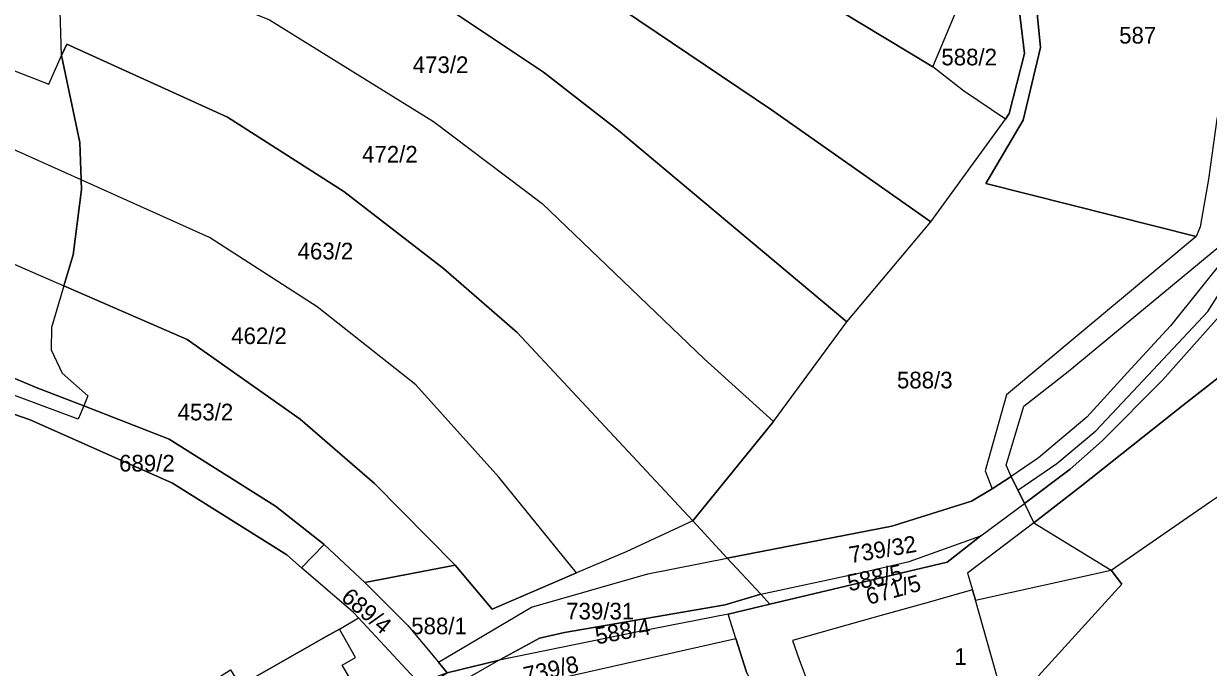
# Model space of a CAD drawing. Extents: x -629983 to -626385, y -1072828 to -1067897.
# Drawn here: x -627150.4 to -626936.7, y -1070145.8 to -1070029.7 of the extents above; entities that cross this region are included whole.
import ezdxf

# ---------------------------------------------------------------- set-up
doc = ezdxf.new("R2010")
doc.units = 0
for name, color, linetype in [('Parcela nároku', 7, 'Continuous'), ('Parcelní číslo', 7, 'Continuous'), ('Plocha PÚ', 7, 'Continuous'), ('Vnitřní obvod_šetřený', 7, 'Continuous'), ('voda', 7, 'Continuous')]:
    doc.layers.add(name, color=color, linetype=linetype)

msp = doc.modelspace()

# ---------------------------------------------------------------- linework, layer by layer
at = {"layer": 'Parcela nároku'}
for points in [[(-627088.59, -1069955.42), (-627120.01, -1069943.03), (-627122.71, -1069947.36), (-627125, -1069952.04), (-627127.45, -1069955.66), (-627129.53, -1069962.1), (-627095.01, -1069975.09), (-627066.59, -1069990.17), (-627033.45, -1070009.1), (-626986.34, -1070037.52), (-626978, -1070017.56), (-627015.68, -1069995.42)], [(-627033.45, -1070009.1), (-627066.59, -1069990.17), (-627095.01, -1069975.09), (-627129.53, -1069962.1), (-627130.33, -1069964.55), (-627134.1, -1069979.16), (-627107.13, -1069989.12), (-627073.62, -1070007.14), (-627060.19, -1070015.09), (-627015.45, -1070045.26), (-626986.73, -1070065.45), (-626973.26, -1070046.97), (-626980.83, -1070041.87), (-626986.34, -1070037.52)], [(-626986.73, -1070065.45), (-627015.45, -1070045.26), (-627060.19, -1070015.09), (-627073.62, -1070007.14), (-627107.13, -1069989.12), (-627134.1, -1069979.16), (-627138.98, -1069998.05), (-627100.4, -1070012.51), (-627079.87, -1070022.88), (-627056.59, -1070038.48), (-627043.05, -1070049), (-627001.87, -1070083.51)], [(-626958.12, -1069999.59), (-626939.49, -1069984.53), (-626922.33, -1070013.79), (-626933.64, -1070040.63), (-626935.11, -1070046.98), (-626936.62, -1070057.77), (-626938.12, -1070066.39), (-626938.87, -1070068.12), (-626976.78, -1070058.57), (-626970.06, -1070047.13), (-626966.93, -1070034), (-626969.36, -1070009.37)], [(-627138.98, -1069998.05), (-627141.62, -1070008.28), (-627142.81, -1070014.22), (-627106.07, -1070029.02), (-627076.47, -1070047.35), (-627056.84, -1070062.14), (-627027.64, -1070090.16), (-627015.09, -1070101.48), (-627001.87, -1070083.51), (-627043.05, -1070049), (-627056.59, -1070038.48), (-627079.87, -1070022.88), (-627100.4, -1070012.51)], [(-626971.36, -1070022.08), (-626969.8, -1070035.12), (-626972.59, -1070045.95), (-626973.26, -1070046.97), (-626980.83, -1070041.87), (-626986.34, -1070037.52), (-626978, -1070017.56), (-626972.67, -1070009.07)], [(-627143.19, -1070014.07), (-627158.09, -1070012.2), (-627163.38, -1070033.87), (-627145.84, -1070040.66), (-627143.56, -1070035.5), (-627143.96, -1070023.4), (-627143.3, -1070016.64), (-627142.81, -1070014.22)], [(-627027.64, -1070090.16), (-627015.09, -1070101.48), (-627029.64, -1070119.37), (-627061.35, -1070085.42), (-627074.63, -1070073.88), (-627092.65, -1070059.98), (-627113.63, -1070046.57), (-627142.64, -1070033.43), (-627143.56, -1070035.5), (-627143.96, -1070023.4), (-627143.3, -1070016.64), (-627142.81, -1070014.22), (-627106.07, -1070029.02), (-627076.47, -1070047.35), (-627056.84, -1070062.14)], [(-626921.43, -1070025.55), (-626914.75, -1070029.07), (-626920.55, -1070046.4), (-626923.16, -1070053.99), (-626928.9, -1070065.21), (-626933.01, -1070071.19), (-626943.45, -1070084.22), (-626950.65, -1070091.98), (-626958.55, -1070100.68), (-626967.28, -1070108.01), (-626972.24, -1070111.41), (-626973.1, -1070109.36), (-626969.94, -1070098.69), (-626961.92, -1070092.47), (-626932.99, -1070068.55), (-626929.34, -1070041.47)], [(-627166.71, -1070046.52), (-627163.38, -1070033.87), (-627145.84, -1070040.66), (-627143.56, -1070035.5), (-627140.29, -1070051.16), (-627140.06, -1070057.9), (-627151.83, -1070052.62)], [(-627092.65, -1070059.98), (-627074.63, -1070073.88), (-627061.35, -1070085.42), (-627029.64, -1070119.37), (-627041.71, -1070124.97), (-627050.63, -1070128.79), (-627064.7, -1070111.53), (-627079.63, -1070094.86), (-627097.43, -1070080.81), (-627116.88, -1070068.28), (-627140.06, -1070057.9), (-627140.29, -1070051.16), (-627143.56, -1070035.5), (-627142.64, -1070033.43), (-627113.63, -1070046.57)], [(-626914.83, -1070045.91), (-626916.3, -1070052.3), (-626918.02, -1070056.37), (-626926.9, -1070072.56), (-626930.91, -1070078.27), (-626944.91, -1070094), (-626955.78, -1070104.97), (-626961.55, -1070110.08), (-626969.82, -1070116.29), (-626968.13, -1070119.78), (-626959.53, -1070113.07), (-626941.17, -1070098.52), (-626930.19, -1070089.96), (-626917.66, -1070080.4), (-626903.57, -1070068.94), (-626908.7, -1070047.45), (-626911.27, -1070036.42)], [(-627140.06, -1070057.9), (-627151.83, -1070052.62), (-627166.71, -1070046.52), (-627171.49, -1070064.68), (-627143.14, -1070077), (-627141.49, -1070071.4), (-627140, -1070059.64)], [(-627141.49, -1070071.4), (-627143.14, -1070077), (-627120.88, -1070086.67), (-627100.52, -1070101.03), (-627087.11, -1070112.66), (-627072.56, -1070127.37), (-627065.9, -1070135.33), (-627050.63, -1070128.79), (-627064.7, -1070111.53), (-627079.63, -1070094.86), (-627097.43, -1070080.81), (-627116.88, -1070068.28), (-627140.06, -1070057.9), (-627140, -1070059.64)], [(-627176.48, -1070084.95), (-627171.49, -1070064.68), (-627143.14, -1070077), (-627145.36, -1070084.53), (-627145.44, -1070088.53), (-627143.44, -1070092.75), (-627138.81, -1070096.85), (-627139.57, -1070098.67), (-627148.15, -1070095.32), (-627155.49, -1070092.28), (-627174.36, -1070085.69)], [(-627143.14, -1070077), (-627145.36, -1070084.53), (-627145.44, -1070088.53), (-627143.44, -1070092.75), (-627138.81, -1070096.85), (-627139.57, -1070098.67), (-627124.14, -1070104.69), (-627104.95, -1070116.75), (-627096.2, -1070123.68), (-627088.83, -1070130.5), (-627072.56, -1070127.37), (-627087.11, -1070112.66), (-627100.52, -1070101.03), (-627120.88, -1070086.67)], [(-627175.67, -1070092.02), (-627174.36, -1070085.69), (-627155.49, -1070092.28), (-627148.15, -1070095.32), (-627139.57, -1070098.67), (-627140.56, -1070101.05), (-627168.06, -1070090.85), (-627171.48, -1070091.1), (-627173.72, -1070092.7)], [(-626967.32, -1070147.34), (-626952.24, -1070130.82), (-626954.18, -1070128.3), (-626936.23, -1070115.91), (-626914.61, -1070101.46), (-626893.72, -1070087.44), (-626878.42, -1070105.68), (-626838.37, -1070153.8), (-626843.54, -1070157.06), (-626848.75, -1070159.57), (-626863.88, -1070171.76), (-626872.99, -1070179.12), (-626887.59, -1070189.96), (-626911.42, -1070210.64), (-626920.06, -1070200.25), (-626930.91, -1070188.7), (-626953.54, -1070165.93)], [(-627179.11, -1070102.43), (-627182.79, -1070129.31), (-627188.17, -1070161.97), (-627164.05, -1070181.7), (-627127.23, -1070158.76), (-627126.21, -1070157.99), (-627114.91, -1070147.41), (-627113.07, -1070146.24), (-627111.33, -1070149.11), (-627095.84, -1070140.28), (-627093.44, -1070138.91), (-627090.01, -1070136.88), (-627090.88, -1070135.94), (-627100.27, -1070127.84), (-627102.93, -1070125.54), (-627123.58, -1070112.62), (-627149.23, -1070101.19), (-627173.72, -1070092.7), (-627175.67, -1070092.02), (-627177.28, -1070091.46)], [(-627168.06, -1070090.85), (-627171.48, -1070091.1), (-627173.72, -1070092.7), (-627149.23, -1070101.19), (-627123.58, -1070112.62), (-627102.93, -1070125.54), (-627100.27, -1070127.84), (-627096.2, -1070123.68), (-627104.95, -1070116.75), (-627124.14, -1070104.69), (-627139.57, -1070098.67), (-627140.56, -1070101.05)], [(-626972.24, -1070111.41), (-626975.64, -1070113.65), (-626979.38, -1070115.84), (-626993.74, -1070120.38), (-627023.44, -1070126.11), (-627017.39, -1070132.64), (-626999.46, -1070128.78), (-626990.66, -1070126.71), (-626977.72, -1070122.1), (-626969.82, -1070116.29)], [(-626969.82, -1070116.29), (-626968.13, -1070119.78), (-626980.11, -1070128.81), (-626979.18, -1070131.84), (-626987.84, -1070134.27), (-626996.76, -1070136.77), (-627011.69, -1070140.96), (-627010.48, -1070144.38), (-627008.5, -1070149.71), (-627014.94, -1070152.06), (-627016.87, -1070152.66), (-627019.96, -1070146.7), (-627021.89, -1070140.64), (-627023.3, -1070136.2), (-627015.8, -1070134.43), (-626983.76, -1070126.87), (-626977.72, -1070122.1)], [(-627072.56, -1070127.37), (-627088.83, -1070130.5), (-627081.08, -1070138.25), (-627075.54, -1070144.91), (-627058.79, -1070134.99), (-627037.79, -1070128.95), (-627023.44, -1070126.11), (-627029.64, -1070119.37), (-627041.71, -1070124.97), (-627050.63, -1070128.79), (-627065.9, -1070135.33)], [(-627017.39, -1070132.64), (-626999.46, -1070128.78), (-626990.66, -1070126.71), (-626977.72, -1070122.1), (-626983.76, -1070126.87), (-627015.8, -1070134.43)], [(-627100.27, -1070127.84), (-627096.2, -1070123.68), (-627088.83, -1070130.5), (-627081.08, -1070138.25), (-627075.54, -1070144.91), (-627074.02, -1070146.81), (-627079.02, -1070148.65), (-627090.01, -1070136.88), (-627090.88, -1070135.94)], [(-627037.79, -1070128.95), (-627023.44, -1070126.11), (-627017.39, -1070132.64), (-627023.83, -1070134.57), (-627052.84, -1070139.54), (-627057.35, -1070140.58), (-627064.59, -1070144.52), (-627074.02, -1070146.81), (-627075.54, -1070144.91), (-627058.79, -1070134.99)], [(-626982.72, -1070148.62), (-626981.69, -1070151.96), (-626974.05, -1070150.14), (-626975.13, -1070146.29), (-626978.67, -1070133.67), (-626954.18, -1070128.3), (-626952.24, -1070130.82), (-626967.32, -1070147.34), (-626953.54, -1070165.93), (-626954.95, -1070167.11), (-626980.99, -1070188.96), (-626994.01, -1070178.49), (-627007.83, -1070162.13), (-627014.94, -1070152.06), (-627008.5, -1070149.71), (-627007.27, -1070149.36), (-627005.37, -1070155.59)], [(-627017.39, -1070132.64), (-627015.8, -1070134.43), (-627023.3, -1070136.2), (-627039.61, -1070139.4), (-627064.59, -1070144.52), (-627057.35, -1070140.58), (-627052.84, -1070139.54), (-627023.83, -1070134.57)], [(-626979.18, -1070131.84), (-626987.84, -1070134.27), (-626996.76, -1070136.77), (-627011.69, -1070140.96), (-627010.48, -1070144.38), (-627008.5, -1070149.71), (-627007.27, -1070149.36), (-627005.37, -1070155.59), (-626982.72, -1070148.62), (-626981.69, -1070151.96), (-626974.05, -1070150.14), (-626975.13, -1070146.29), (-626978.67, -1070133.67)], [(-627064.59, -1070144.52), (-627091.23, -1070159.74), (-627106.48, -1070167.33), (-627093.12, -1070162.31), (-627081.7, -1070156.55), (-627074.7, -1070152.35), (-627051, -1070147.18), (-627021.89, -1070140.64), (-627023.3, -1070136.2), (-627039.61, -1070139.4)], [(-627093.44, -1070138.91), (-627090.01, -1070136.88), (-627079.02, -1070148.65), (-627088.6, -1070152.71), (-627092.94, -1070145.4), (-627090.54, -1070144.04)], [(-627090.54, -1070144.04), (-627093.44, -1070138.91), (-627095.84, -1070140.28), (-627111.33, -1070149.11), (-627108.45, -1070154.14), (-627100.65, -1070149.75), (-627097.19, -1070155.5), (-627091.34, -1070153.87), (-627088.6, -1070152.71), (-627092.94, -1070145.4)]]:
    msp.add_lwpolyline(points, close=True, dxfattribs=at)
for points in [[(-626969.36, -1070009.37), (-626966.93, -1070034), (-626970.06, -1070047.13), (-626976.78, -1070058.57), (-626938.87, -1070068.12), (-626973.09, -1070096.67), (-626976.92, -1070110.37), (-626975.64, -1070113.65), (-626979.38, -1070115.84), (-626993.74, -1070120.38), (-627023.44, -1070126.11), (-627029.64, -1070119.37), (-627015.09, -1070101.48), (-627001.87, -1070083.51), (-626986.73, -1070065.45), (-626973.26, -1070046.97), (-626972.59, -1070045.95), (-626969.8, -1070035.12), (-626971.36, -1070022.08)], [(-626936.62, -1070057.77), (-626938.12, -1070066.39), (-626938.87, -1070068.12), (-626973.09, -1070096.67), (-626976.92, -1070110.37), (-626975.64, -1070113.65), (-626972.24, -1070111.41), (-626973.1, -1070109.36), (-626969.94, -1070098.69), (-626961.92, -1070092.47), (-626932.99, -1070068.55)], [(-626933.01, -1070071.19), (-626943.45, -1070084.22), (-626950.65, -1070091.98), (-626958.55, -1070100.68), (-626967.28, -1070108.01), (-626972.24, -1070111.41), (-626969.82, -1070116.29), (-626961.55, -1070110.08), (-626955.78, -1070104.97), (-626944.91, -1070094), (-626930.91, -1070078.27)], [(-626930.19, -1070089.96), (-626941.17, -1070098.52), (-626959.53, -1070113.07), (-626968.13, -1070119.78), (-626980.11, -1070128.81), (-626979.18, -1070131.84), (-626978.67, -1070133.67), (-626954.18, -1070128.3), (-626936.23, -1070115.91)], [(-627051, -1070147.18), (-627021.89, -1070140.64), (-627019.96, -1070146.7)], [(-627165.66, -1070194.76), (-627145.34, -1070182.16), (-627120.06, -1070168.31), (-627091.34, -1070153.87), (-627088.6, -1070152.71), (-627078.16, -1070149.32), (-627074.02, -1070146.81), (-627064.59, -1070144.52), (-627091.23, -1070159.74), (-627106.48, -1070167.33), (-627109.87, -1070168.86), (-627116.09, -1070170.94), (-627130.96, -1070179.7), (-627147.78, -1070191.28), (-627160.19, -1070197.81)]]:
    msp.add_lwpolyline(points, dxfattribs=at)
at = {"layer": 'Plocha PÚ'}
msp.add_lwpolyline([(-627167.6, -1070094.82), (-627149.23, -1070101.19), (-627123.58, -1070112.62), (-627102.93, -1070125.54), (-627100.27, -1070127.84), (-627096.2, -1070123.68), (-627088.83, -1070130.5), (-627081.08, -1070138.25), (-627075.54, -1070144.91), (-627058.79, -1070134.99), (-627037.79, -1070128.95), (-627023.44, -1070126.11), (-626993.74, -1070120.38), (-626979.38, -1070115.84), (-626975.64, -1070113.65), (-626972.24, -1070111.41), (-626969.82, -1070116.29), (-626968.13, -1070119.78), (-626954.18, -1070128.3), (-626952.24, -1070130.82), (-626967.32, -1070147.34)], dxfattribs=at)
at = {"layer": 'Vnitřní obvod_šetřený'}
for p, q in [((-627177.28, -1070091.46), (-627149.23, -1070101.19)), ((-627149.23, -1070101.19), (-627123.58, -1070112.62)), ((-626975.64, -1070113.65), (-626972.24, -1070111.41)), ((-626972.24, -1070111.41), (-626969.82, -1070116.29)), ((-627123.58, -1070112.62), (-627102.93, -1070125.54)), ((-626979.38, -1070115.84), (-626975.64, -1070113.65)), ((-626993.74, -1070120.38), (-626979.38, -1070115.84)), ((-626969.82, -1070116.29), (-626968.13, -1070119.78)), ((-627023.44, -1070126.11), (-626993.74, -1070120.38)), ((-626968.13, -1070119.78), (-626954.18, -1070128.3)), ((-627100.27, -1070127.84), (-627096.2, -1070123.68)), ((-627096.2, -1070123.68), (-627088.83, -1070130.5)), ((-627102.93, -1070125.54), (-627100.27, -1070127.84)), ((-627037.79, -1070128.95), (-627023.44, -1070126.11)), ((-627058.79, -1070134.99), (-627037.79, -1070128.95)), ((-626954.18, -1070128.3), (-626952.24, -1070130.82)), ((-627088.83, -1070130.5), (-627081.08, -1070138.25)), ((-626952.24, -1070130.82), (-626967.32, -1070147.34)), ((-627075.54, -1070144.91), (-627058.79, -1070134.99)), ((-627081.08, -1070138.25), (-627075.54, -1070144.91))]:
    msp.add_line(p, q, dxfattribs=at)
at = {"layer": 'voda'}
msp.add_lwpolyline([(-626971.03, -1070113.85), (-626964.01, -1070109.05), (-626956.93, -1070103.18), (-626949.33, -1070095.07), (-626936.72, -1070081.61), (-626924.36, -1070062.15)], dxfattribs=at)

# ---------------------------------------------------------------- texts
at = {"layer": 'Parcelní číslo'}
for s, p in [('587', (-626952.74, -1070033.32)), ('588/2', (-626984.82, -1070037.25)), ('473/2', (-627080.2, -1070038.63)), ('472/2', (-627089.35, -1070054.78)), ('463/2', (-627100.98, -1070072.24)), ('462/2', (-627112.96, -1070087.52)), ('588/3', (-626992.83, -1070095.5)), ('453/2', (-627122.63, -1070101.27)), ('689/2', (-627133.19, -1070110.5)), ('739/31', (-627052.51, -1070137.17)), ('588/1', (-627080.48, -1070139.85)), ('1', (-626982.47, -1070145.37))]:
    msp.add_text(s, height=3, dxfattribs=at).set_placement(p)
for s, rotation, p in [('739/32', 9.8186, (-627001.2, -1070127.05)), ('588/5', 11.624, (-627001.44, -1070132.11)), ('671/5', 15.2449, (-626997.95, -1070134.56)), ('689/4', 319.6217, (-627093.32, -1070133.53)), ('588/4', 10.5053, (-627046.98, -1070141.69)), ('739/8', 12.4881, (-627059.84, -1070148.76))]:
    msp.add_text(s, height=3, rotation=rotation, dxfattribs=at).set_placement(p)

doc.saveas('drawing.dxf')
